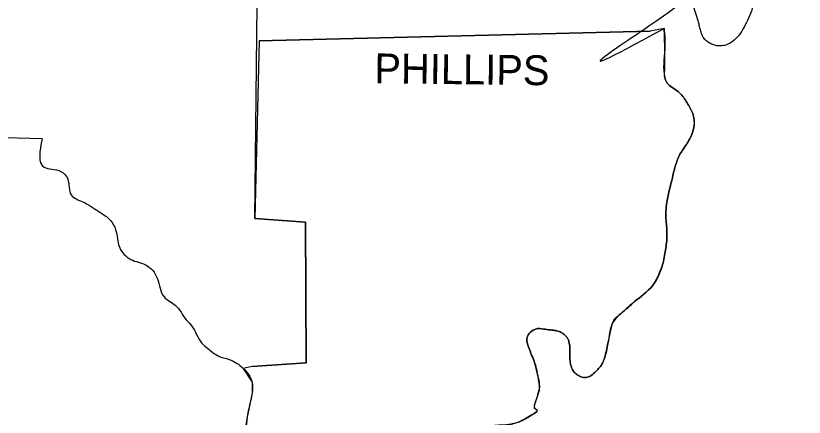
# Model space of a CAD drawing. Extents: x -31696 to 27919, y -8775 to 11152.
# Drawn here: x 14782 to 15894, y 6995 to 7561 of the extents above; entities that cross this region are included whole.
import ezdxf

# ---------------------------------------------------------------- set-up
doc = ezdxf.new("R2010")
doc.units = 0
for name, color, linetype in [('Level 1', 7, 'Continuous'), ('Level 2', 7, 'Continuous'), ('Level 48', 7, 'Continuous')]:
    doc.layers.add(name, color=color, linetype=linetype)

msp = doc.modelspace()

# ---------------------------------------------------------------- linework, layer by layer
at = {"layer": 'Level 1'}
for points in [[(15115.0672281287, 7066.62009515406), (15191.382959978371, 7071.51212930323), (15190.404553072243, 7270.128713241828), (15118.980855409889, 7275.020747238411), (15122.894482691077, 7663.44825379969), (15061.254853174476, 7672.253915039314), (15059.298039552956, 7933.488535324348), (15893.879054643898, 7939.358976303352)], [(15124.8512963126, 7525.492892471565), (15676.672741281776, 7539.190587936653)], [(14818.609962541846, 7387.537531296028), (14448.772185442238, 7397.32159944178), (14446.815371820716, 7276.977560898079), (13698.334156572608, 7274.042340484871)]]:
    msp.add_lwpolyline(points, dxfattribs=at)
for points in [[(15832.23942520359, 7702.5845265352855), (15822.270791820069, 7686.305918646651), (15816.074835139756, 7679.504678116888), (15809.736068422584, 7674.210728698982), (15791.636851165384, 7676.0700440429), (15782.452095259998, 7682.965339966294), (15778.906444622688, 7687.243003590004), (15776.470236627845, 7691.822051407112), (15775.057825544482, 7703.581623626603), (15776.470236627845, 7715.303815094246), (15777.70232238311, 7721.439728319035), (15779.520050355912, 7727.558870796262), (15781.035880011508, 7733.665528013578), (15781.362270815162, 7739.763985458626), (15777.127306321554, 7748.595807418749), (15773.4617785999, 7752.309392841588), (15769.621388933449, 7755.418494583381), (15764.25334750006, 7757.088471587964), (15757.70452274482, 7756.23210957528), (15751.977495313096, 7753.256728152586), (15749.074845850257, 7748.5696469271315), (15748.514513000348, 7740.989654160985), (15748.73309179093, 7733.401167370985), (15749.122547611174, 7725.8142674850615), (15749.074845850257, 7718.23903543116), (15747.118032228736, 7688.886831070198), (15745.672834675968, 7678.3171045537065), (15743.5353942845, 7667.79062985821), (15741.25367244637, 7652.053523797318), (15741.184956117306, 7649.434198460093), (15741.24759128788, 7646.815337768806), (15745.912201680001, 7638.821642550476), (15750.259569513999, 7635.973621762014), (15754.94528660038, 7634.096049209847), (15762.754223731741, 7632.485752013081), (15770.607306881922, 7631.7397345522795), (15778.45663443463, 7631.193467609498), (15786.254304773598, 7630.182421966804), (15797.606672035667, 7628.262178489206), (15803.21105949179, 7626.775998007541), (15808.757661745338, 7624.311981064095), (15818.055878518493, 7614.538059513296), (15820.72780863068, 7608.308232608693), (15822.455356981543, 7601.808624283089), (15823.638720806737, 7588.026087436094), (15821.476950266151, 7574.413233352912), (15810.714475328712, 7547.996249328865), (15795.05996628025, 7526.471299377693), (15783.093474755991, 7519.633248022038), (15776.703669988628, 7518.377022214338), (15770.599795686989, 7518.644044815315), (15759.634335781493, 7522.725636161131), (15754.74403934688, 7526.455656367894), (15751.031659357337, 7531.3633333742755), (15748.35134044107, 7537.699634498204), (15746.570618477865, 7544.097081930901), (15745.063603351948, 7550.487299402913), (15743.204404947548, 7556.801910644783), (15739.69530355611, 7568.091148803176), (15734.39874351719, 7579.305267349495), (15730.477299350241, 7584.912679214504), (15726.278575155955, 7590.190340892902), (15717.76582767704, 7595.938183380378), (15713.239049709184, 7594.418837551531), (15708.707264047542, 7589.992495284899), (15704.30192951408, 7583.891564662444), (15702.187762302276, 7580.598256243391), (15700.154504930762, 7577.348453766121), (15695.413943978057, 7560.256490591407), (15696.24087768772, 7543.104215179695), (15696.240877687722, 7543.1042151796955)], [(15696.240877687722, 7543.1042151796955), (15697.219284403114, 7513.752010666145), (15697.219284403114, 7473.637331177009), (15700.656797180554, 7465.810943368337), (15707.716229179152, 7459.725605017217), (15715.88683310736, 7453.991883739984), (15722.657861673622, 7447.220347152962), (15727.53768010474, 7439.933981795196), (15732.103695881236, 7432.478710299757), (15738.312370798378, 7416.889735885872), (15733.42033676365, 7389.494344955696), (15728.888917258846, 7381.2615398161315), (15723.626213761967, 7373.474502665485), (15718.613139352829, 7365.62553040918), (15714.830607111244, 7357.206919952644), (15707.003352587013, 7328.833122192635), (15699.176098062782, 7290.675256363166), (15698.598906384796, 7280.207535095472), (15699.22580812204, 7269.675692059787), (15700.072456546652, 7259.125757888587), (15700.154504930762, 7248.6037632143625), (15697.839816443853, 7227.974195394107), (15693.305657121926, 7207.510676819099), (15679.607961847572, 7180.115285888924), (15654.169384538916, 7157.6119291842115), (15637.536468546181, 7142.935826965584), (15623.838773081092, 7128.259724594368), (15616.989925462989, 7098.907520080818), (15612.097891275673, 7078.3609769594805), (15609.393996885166, 7071.305962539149), (15605.149608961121, 7064.9789294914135), (15599.731929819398, 7059.227877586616), (15593.508161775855, 7053.9008065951), (15586.265070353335, 7050.970481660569), (15578.832059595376, 7051.943992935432), (15567.091177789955, 7061.728061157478), (15563.177550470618, 7078.3609769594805), (15563.040399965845, 7082.508372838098), (15563.232061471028, 7086.673104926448), (15563.396467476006, 7090.840001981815), (15563.177550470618, 7094.993892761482), (15561.08847299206, 7103.855229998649), (15558.845276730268, 7107.924125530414), (15555.350295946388, 7111.626808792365), (15549.407022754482, 7115.256661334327), (15543.313785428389, 7117.057021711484), (15537.123760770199, 7117.854487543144), (15530.890125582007, 7118.475656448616), (15521.101431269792, 7119.87059784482), (15516.178565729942, 7119.535914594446), (15511.32198921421, 7117.497249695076), (15504.642324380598, 7111.264166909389), (15502.516327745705, 7103.799554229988), (15504.843711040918, 7094.343168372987), (15508.393216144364, 7084.900279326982), (15512.18409923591, 7075.367561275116), (15515.2356164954, 7065.64168840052), (15517.945149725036, 7053.412264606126), (15520.12765049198, 7041.181517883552), (15519.804152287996, 7032.8582383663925), (15517.423334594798, 7024.538951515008), (15514.682462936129, 7016.224489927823), (15513.278802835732, 7007.915686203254), (15514.059539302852, 7006.69959728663), (15515.714491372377, 7005.700144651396), (15517.130005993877, 7004.8300559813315), (15517.19243011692, 7004.002058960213), (15509.55313243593, 6998.193651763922), (15500.976167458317, 6992.979919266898), (15481.969784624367, 6985.41232926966), (15474.863785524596, 6984.196048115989), (15467.732638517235, 6983.758945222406), (15460.626615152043, 6983.414729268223), (15453.595986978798, 6982.477108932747), (15430.11422332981, 6975.6282611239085), (15407.610866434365, 6960.952158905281), (15404.30349851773, 6955.835124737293), (15402.08711508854, 6950.149090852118), (15399.941988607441, 6944.483353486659), (15396.848391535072, 6939.427208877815), (15381.193882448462, 6921.815886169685), (15367.496186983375, 6905.182970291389), (15348.906457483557, 6897.355715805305), (15328.359914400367, 6901.269343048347), (15314.6787378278, 6903.768916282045), (15307.805396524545, 6904.505431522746), (15304.378355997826, 6904.517257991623), (15300.964523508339, 6904.204563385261), (15295.402620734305, 6901.732913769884), (15291.023082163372, 6896.886307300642), (15287.700636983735, 6890.806794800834), (15285.310014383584, 6884.636427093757), (15284.387190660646, 6870.250821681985), (15290.202048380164, 6856.262629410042), (15308.79177803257, 6839.629713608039), (15315.541961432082, 6836.439451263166), (15322.31734082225, 6833.875660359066), (15336.18716877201, 6831.802459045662), (15364.560966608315, 6833.759272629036), (15391.956357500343, 6836.694493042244), (15398.977107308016, 6835.829548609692), (15405.61890371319, 6832.7663451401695), (15411.789071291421, 6828.242791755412), (15417.394934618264, 6822.996797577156), (15420.435088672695, 6816.91540976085), (15420.172649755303, 6809.5636684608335), (15412.502900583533, 6796.579813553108), (15406.77604487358, 6792.242855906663), (15400.863387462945, 6788.6094633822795), (15388.042730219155, 6783.860524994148), (15351.84167785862, 6779.946897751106), (15344.504082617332, 6780.391841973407), (15337.165874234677, 6781.364809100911), (15329.827516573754, 6782.36262563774), (15322.489473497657, 6782.88211808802), (15304.75970115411, 6781.676106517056), (15296.002850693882, 6779.272288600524), (15287.26682804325, 6775.054863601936), (15276.086354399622, 6764.823291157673), (15272.330797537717, 6758.782618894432), (15270.859348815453, 6755.72531024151)], [(14818.609962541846, 7387.537531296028), (14821.545182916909, 7347.422851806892), (14845.026946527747, 7341.552410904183), (14854.811014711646, 7330.789935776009), (14859.703048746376, 7308.286579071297), (14876.335964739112, 7298.502510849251), (14898.839321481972, 7284.804815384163), (14912.537016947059, 7275.020747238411), (14922.321085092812, 7259.366238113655), (14928.191526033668, 7233.927660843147), (14943.846035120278, 7217.294745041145), (14965.370985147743, 7209.467490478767), (14981.02549423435, 7190.877761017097), (14990.809562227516, 7164.460776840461), (15006.464071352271, 7152.71989518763), (15022.11858043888, 7132.173351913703), (15029.945834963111, 7123.367690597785), (15043.643530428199, 7099.885926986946), (15057.341225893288, 7088.145045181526), (15067.125294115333, 7081.296197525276), (15082.779803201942, 7076.404163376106), (15102.34793956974, 7063.684874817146), (15115.0672281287, 7044.116738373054), (15115.0672281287, 7029.440636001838), (15110.175194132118, 7006.937279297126), (15106.26156685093, 6983.455515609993), (15104.304753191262, 6957.038531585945), (15102.34793956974, 6933.556767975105), (15111.153600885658, 6913.988631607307), (15106.26156685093, 6884.636427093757), (15096.47749866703, 6868.98191812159), (15095.499091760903, 6847.456968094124), (15092.56387138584, 6815.169543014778), (15088.650244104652, 6796.579813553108), (15079.844582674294, 6766.249202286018), (15067.125294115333, 6750.5946931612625)]]:
    msp.add_spline(points, degree=3, dxfattribs=at)
at = {"layer": 'Level 48'}
for p, q in [((15696.240877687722, 7543.1042151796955), (15676.672741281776, 7539.190587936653)), ((15696.240877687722, 7543.1042151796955), (15676.672741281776, 7539.190587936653)), ((15676.672741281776, 7539.190587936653), (15124.8512963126, 7525.492892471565))]:
    msp.add_line(p, q, dxfattribs=at)
msp.add_lwpolyline([(15124.8512963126, 7525.492892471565), (15118.980855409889, 7275.020747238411), (15190.404553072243, 7270.128713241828), (15191.382959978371, 7071.51212930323), (15115.0672281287, 7066.62009515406), (15102.34793956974, 7063.684874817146), (15115.0672281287, 7044.116738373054), (15115.0672281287, 7029.440636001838), (15108.218380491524, 6995.196397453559), (15105.283160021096, 6970.247023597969)], dxfattribs=at)
msp.add_lwpolyline([(15124.8512963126, 7525.492892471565), (15118.980855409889, 7275.020747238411), (15190.404553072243, 7270.128713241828), (15191.382959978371, 7071.51212930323), (15115.0672281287, 7066.62009515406), (15102.34793956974, 7063.684874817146), (15115.0672281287, 7044.116738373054), (15115.0672281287, 7029.440636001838), (15108.218380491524, 6995.196397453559), (15105.283160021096, 6970.247023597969)], dxfattribs=at)
for points in [[(15693.090768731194, 7206.756278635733), (15693.305657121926, 7207.510676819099), (15697.839816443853, 7227.974195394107), (15699.273139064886, 7238.272167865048), (15700.154504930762, 7248.6037632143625), (15700.072456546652, 7259.125757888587), (15699.22580812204, 7269.675692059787), (15698.598906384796, 7280.207535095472), (15699.176098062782, 7290.675256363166), (15707.003352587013, 7328.833122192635), (15714.830607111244, 7357.206919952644), (15718.613139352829, 7365.62553040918), (15723.626213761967, 7373.474502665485), (15728.888917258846, 7381.2615398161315), (15733.42033676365, 7389.494344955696), (15738.067601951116, 7403.102274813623), (15738.312370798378, 7416.889735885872), (15737.300487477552, 7420.883964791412), (15735.888672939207, 7424.84685985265), (15732.103695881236, 7432.478710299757), (15727.53768010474, 7439.933981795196), (15722.657861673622, 7447.220347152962), (15715.88683310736, 7453.991883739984), (15707.716229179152, 7459.725605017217), (15700.656797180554, 7465.810943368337), (15697.219284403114, 7473.637331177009), (15697.086220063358, 7483.666037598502), (15697.21018790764, 7493.696553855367), (15697.338703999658, 7503.726128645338), (15697.219284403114, 7513.752010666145), (15696.240877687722, 7543.1042151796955)], [(15510.239382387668, 7080.277405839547), (15508.393216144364, 7084.900279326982), (15504.843711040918, 7094.343168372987), (15502.516327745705, 7103.799554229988), (15504.642324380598, 7111.264166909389), (15511.32198921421, 7117.497249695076), (15516.178565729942, 7119.535914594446), (15521.101431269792, 7119.87059784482), (15530.890125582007, 7118.475656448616), (15537.123760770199, 7117.854487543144), (15543.313785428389, 7117.057021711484), (15549.407022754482, 7115.256661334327), (15555.350295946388, 7111.626808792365), (15558.845276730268, 7107.924125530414), (15561.08847299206, 7103.855229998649), (15563.177550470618, 7094.993892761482), (15563.396467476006, 7090.840001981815), (15563.232061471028, 7086.673104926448), (15563.040399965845, 7082.508372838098), (15563.177550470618, 7078.3609769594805), (15564.230967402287, 7069.954442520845), (15567.091177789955, 7061.728061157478), (15572.0320143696, 7055.842704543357), (15575.262474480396, 7053.726800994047), (15578.832059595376, 7051.943992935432), (15586.265070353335, 7050.970481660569), (15593.508161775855, 7053.9008065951), (15599.731929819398, 7059.227877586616), (15605.149608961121, 7064.9789294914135), (15609.393996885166, 7071.305962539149), (15612.097891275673, 7078.3609769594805), (15616.989925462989, 7098.907520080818), (15620.322605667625, 7113.5936977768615), (15622.013636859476, 7120.935527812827), (15622.903927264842, 7124.600617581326), (15623.838773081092, 7128.259724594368), (15637.536468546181, 7142.935826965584), (15654.169384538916, 7157.6119291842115), (15679.607961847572, 7180.115285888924), (15693.090768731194, 7206.756278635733)]]:
    msp.add_spline(points, degree=3, dxfattribs=at)
msp.add_open_spline([(15287.136638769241, 6889.566951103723), (15287.317458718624, 6889.981343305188), (15287.505271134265, 6890.3944382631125), (15287.700636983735, 6890.806794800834), (15288.701291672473, 6892.918865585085), (15289.771415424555, 6894.903821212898), (15291.023082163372, 6896.886307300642), (15292.203221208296, 6898.755502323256), (15293.57207759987, 6900.337457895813), (15295.402620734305, 6901.732913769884), (15297.108218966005, 6903.033121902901), (15298.946990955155, 6903.879039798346), (15300.964523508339, 6904.204563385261), (15302.100891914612, 6904.387913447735), (15303.235963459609, 6904.494519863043), (15304.378355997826, 6904.517257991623), (15305.520394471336, 6904.539989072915), (15306.664882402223, 6904.575796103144), (15307.805396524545, 6904.505431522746), (15310.10591585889, 6904.363499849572), (15312.407268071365, 6904.171775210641), (15314.6787378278, 6903.768916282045), (15319.248707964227, 6902.958404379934), (15323.80047124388, 6902.106398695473), (15328.359914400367, 6901.269343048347), (15335.216942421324, 6900.010480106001), (15342.059639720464, 6898.584563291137), (15348.906457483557, 6897.355715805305), (15355.509211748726, 6896.170672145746), (15362.605537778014, 6900.098463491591), (15367.496186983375, 6905.182970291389), (15372.720665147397, 6910.614538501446), (15376.490605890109, 6916.409705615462), (15381.193882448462, 6921.815886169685), (15386.337203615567, 6927.727875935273), (15391.793413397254, 6933.366228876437), (15396.848391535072, 6939.427208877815), (15398.120005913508, 6940.951889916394), (15399.222481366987, 6942.640738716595), (15399.941988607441, 6944.483353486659), (15400.67736772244, 6946.366615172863), (15401.36320299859, 6948.263843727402), (15402.08711508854, 6950.149090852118), (15402.816344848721, 6952.048186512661), (15403.553767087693, 6953.941978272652), (15404.30349851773, 6955.835124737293), (15405.052014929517, 6957.725203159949), (15406.152317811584, 6959.399435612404), (15407.610866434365, 6960.952158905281), (15414.042275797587, 6967.798827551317), (15421.62203765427, 6972.322238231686), (15430.11422332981, 6975.6282611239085), (15437.84590236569, 6978.638217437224), (15445.529042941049, 6981.110786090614), (15453.595986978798, 6982.477108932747), (15455.935211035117, 6982.873310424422), (15458.265488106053, 6983.284548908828), (15460.626615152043, 6983.414729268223), (15462.994893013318, 6983.545303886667), (15465.364595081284, 6983.630914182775), (15467.732638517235, 6983.758945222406), (15470.110725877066, 6983.887519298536), (15472.487100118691, 6984.035034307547), (15474.863785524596, 6984.196048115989), (15477.26202985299, 6984.358522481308), (15479.620596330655, 6984.804632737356), (15481.969784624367, 6985.41232926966), (15488.635946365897, 6987.136756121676), (15494.890770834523, 6989.742635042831), (15500.976167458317, 6992.979919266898), (15503.961909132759, 6994.568261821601), (15506.709566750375, 6996.37645295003), (15509.55313243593, 6998.193651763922), (15512.271874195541, 6999.931081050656), (15514.841112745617, 7001.873570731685), (15517.19243011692, 7004.002058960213), (15517.395876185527, 7004.186224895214), (15517.364800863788, 7004.682911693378), (15517.130005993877, 7004.8300559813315), (15516.660175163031, 7005.124495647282), (15516.187937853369, 7005.412317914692), (15515.714491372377, 7005.700144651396), (15515.163601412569, 7006.035052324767), (15514.610020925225, 7006.357175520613), (15514.059539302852, 7006.69959728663), (15513.648062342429, 7006.955552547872), (15513.306469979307, 7007.447707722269), (15513.278802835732, 7007.915686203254), (15513.117476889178, 7010.644448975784), (15513.824038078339, 7013.5492303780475), (15514.682462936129, 7016.224489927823), (15515.574306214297, 7019.003897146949), (15516.55208667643, 7021.7507782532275), (15517.423334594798, 7024.538951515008), (15518.284498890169, 7027.2948551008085), (15519.112988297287, 7030.03699668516), (15519.804152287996, 7032.8582383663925), (15520.469461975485, 7035.5739461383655), (15520.527991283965, 7038.440911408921), (15520.12765049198, 7041.181517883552), (15519.530522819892, 7045.269265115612), (15518.793990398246, 7049.348812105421), (15517.945149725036, 7053.412264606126), (15517.089337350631, 7057.509091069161), (15516.2659901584, 7061.587991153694), (15515.2356164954, 7065.64168840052), (15514.397123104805, 7068.940490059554), (15513.397841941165, 7072.190332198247), (15512.18409923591, 7075.367561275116), (15511.555397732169, 7077.01332086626), (15510.89826292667, 7078.645874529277), (15510.239382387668, 7080.277405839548)], degree=3, dxfattribs=at)

# ---------------------------------------------------------------- texts
at = {"layer": 'Level 2'}
msp.add_text('PHILLIPS', height=42.06170907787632, rotation=359.31793888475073, dxfattribs=at).set_placement((15287.26682804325, 7465.810076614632))

doc.saveas('drawing.dxf')
